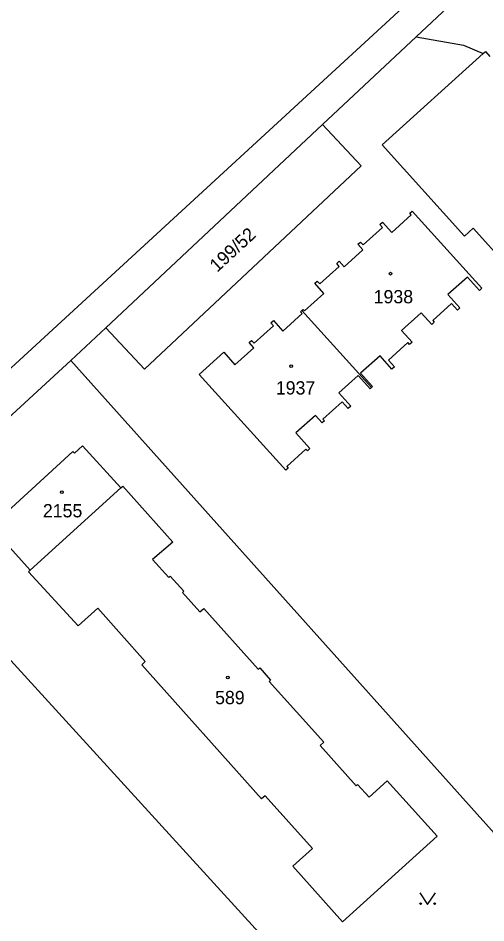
# Model space of a CAD drawing. Extents: x -735249 to -729401, y -1124843 to -1121828.
# Drawn here: x -733187.6 to -733127.6, y -1123687.3 to -1123571.3 of the extents above; entities that cross this region are included whole.
import ezdxf

# ---------------------------------------------------------------- set-up
doc = ezdxf.new("R2010")
doc.units = 0
for name, color, linetype in [('Vrstva 1', 7, 'Continuous'), ('Vrstva 18', 7, 'Continuous'), ('Vrstva 19', 7, 'Continuous'), ('Vrstva 25', 7, 'Continuous'), ('Vrstva 4', 7, 'Continuous')]:
    doc.layers.add(name, color=color, linetype=linetype)

msp = doc.modelspace()

# ---------------------------------------------------------------- linework, layer by layer
at = {"layer": 'Vrstva 1'}
for points in [[(-733136.55, -1123573.69), (-733127.8, -1123565.48)], [(-733195.46, -1123622.51), (-733137.81, -1123569.53)], [(-733136.55, -1123573.69), (-733148.57, -1123584.95)], [(-733136.55, -1123573.69), (-733130.49, -1123574.79)], [(-733130.49, -1123574.79), (-733127.95, -1123575.86)], [(-733140.9, -1123587.54), (-733127.95, -1123575.86)], [(-733148.57, -1123584.95), (-733176.35, -1123611.01)], [(-733148.57, -1123584.95), (-733143.6, -1123590.26)], [(-733130.35, -1123599.25), (-733140.9, -1123587.54)], [(-733143.6, -1123590.26), (-733171.38, -1123616.32)], [(-733139.67, -1123598.8), (-733137.17, -1123596.54)], [(-733137.37, -1123596.32), (-733137.06, -1123596.04)], [(-733137.17, -1123596.54), (-733137.37, -1123596.32)], [(-733137.06, -1123596.04), (-733128.11, -1123605.94)], [(-733143.36, -1123600.38), (-733140.86, -1123598.13)], [(-733141.19, -1123597.76), (-733140.87, -1123597.47)], [(-733140.86, -1123598.13), (-733141.19, -1123597.76)], [(-733140.87, -1123597.47), (-733139.67, -1123598.8)], [(-733129.22, -1123598.23), (-733130.35, -1123599.25)], [(-733124.9, -1123603.03), (-733129.22, -1123598.23)], [(-733144.02, -1123600.3), (-733143.7, -1123600.01)], [(-733143.39, -1123601.01), (-733144.02, -1123600.3)], [(-733143.7, -1123600.01), (-733143.36, -1123600.38)], [(-733145.79, -1123603.18), (-733143.39, -1123601.01)], [(-733146.74, -1123602.76), (-733146.42, -1123602.47)], [(-733146.41, -1123603.13), (-733146.74, -1123602.76)], [(-733146.42, -1123602.47), (-733145.79, -1123603.18)], [(-733148.91, -1123605.38), (-733146.41, -1123603.13)], [(-733149.55, -1123605.29), (-733149.24, -1123605.01)], [(-733149.24, -1123605.01), (-733148.91, -1123605.38)], [(-733129.97, -1123604.51), (-733132.47, -1123606.76)], [(-733128.43, -1123606.23), (-733129.97, -1123604.51)], [(-733148.38, -1123606.6), (-733149.55, -1123605.29)], [(-733128.11, -1123605.94), (-733128.43, -1123606.23)], [(-733150.87, -1123608.85), (-733148.38, -1123606.6)], [(-733132.47, -1123606.76), (-733130.93, -1123608.47)], [(-733151.22, -1123608.81), (-733151.05, -1123608.66)], [(-733151.05, -1123608.66), (-733150.87, -1123608.85)], [(-733132.01, -1123607.91), (-733134.42, -1123610.08)], [(-733131.25, -1123608.76), (-733132.01, -1123607.91)], [(-733130.93, -1123608.47), (-733131.25, -1123608.76)], [(-733153.66, -1123611.42), (-733151.17, -1123609.18)], [(-733151.37, -1123608.95), (-733151.22, -1123608.81)], [(-733151.17, -1123609.18), (-733151.37, -1123608.95)], [(-733151.22, -1123608.81), (-733142.3, -1123618.68)], [(-733135.9, -1123609.08), (-733138.43, -1123611.34)], [(-733134.54, -1123610.59), (-733135.9, -1123609.08)], [(-733180.84, -1123615.22), (-733176.35, -1123611.01)], [(-733171.38, -1123616.32), (-733176.35, -1123611.01)], [(-733157.33, -1123612.99), (-733154.84, -1123610.74)], [(-733155.18, -1123610.37), (-733154.86, -1123610.08)], [(-733154.84, -1123610.74), (-733155.18, -1123610.37)], [(-733154.86, -1123610.08), (-733153.66, -1123611.42)], [(-733134.22, -1123610.3), (-733134.54, -1123610.59)], [(-733134.42, -1123610.08), (-733134.22, -1123610.3)], [(-733138.43, -1123611.34), (-733137.07, -1123612.86)], [(-733157.99, -1123612.9), (-733157.67, -1123612.62)], [(-733157.39, -1123613.57), (-733157.99, -1123612.9)], [(-733157.67, -1123612.62), (-733157.33, -1123612.99)], [(-733137.61, -1123612.9), (-733140.11, -1123615.14)], [(-733137.39, -1123613.14), (-733137.61, -1123612.9)], [(-733137.07, -1123612.86), (-733137.39, -1123613.14)], [(-733164.39, -1123617), (-733161.22, -1123614.14)], [(-733161.22, -1123614.14), (-733159.79, -1123615.74)], [(-733159.79, -1123615.74), (-733157.39, -1123613.57)], [(-733201.34, -1123634.01), (-733180.84, -1123615.22)], [(-733180.84, -1123615.22), (-733120.65, -1123682.36)], [(-733141.18, -1123614.59), (-733143.67, -1123616.83)], [(-733139.65, -1123616.3), (-733141.18, -1123614.59)], [(-733140.11, -1123615.14), (-733139.33, -1123616.01)], [(-733143.67, -1123616.83), (-733142.13, -1123618.53)], [(-733139.33, -1123616.01), (-733139.65, -1123616.3)], [(-733153.28, -1123629.28), (-733164.39, -1123617)], [(-733143.99, -1123617.12), (-733146.49, -1123619.36)], [(-733142.46, -1123618.83), (-733143.99, -1123617.12)], [(-733142.3, -1123618.68), (-733142.46, -1123618.83)], [(-733142.13, -1123618.53), (-733142.3, -1123618.68)], [(-733146.49, -1123619.36), (-733144.95, -1123621.07)], [(-733146.05, -1123620.51), (-733148.5, -1123622.71)], [(-733145.28, -1123621.36), (-733146.05, -1123620.51)], [(-733144.95, -1123621.07), (-733145.28, -1123621.36)], [(-733149.48, -1123622.25), (-733151.97, -1123624.48)], [(-733148.62, -1123623.21), (-733149.48, -1123622.25)], [(-733148.3, -1123622.93), (-733148.62, -1123623.21)], [(-733148.5, -1123622.71), (-733148.3, -1123622.93)], [(-733151.97, -1123624.48), (-733150.17, -1123626.49)], [(-733180.39, -1123627.09), (-733179.34, -1123626.15)], [(-733179.34, -1123626.15), (-733174.43, -1123631.54)], [(-733190.1, -1123635.52), (-733180.6, -1123626.87)], [(-733180.6, -1123626.87), (-733180.39, -1123627.09)], [(-733150.69, -1123626.55), (-733153.16, -1123628.77)], [(-733150.49, -1123626.77), (-733150.69, -1123626.55)], [(-733150.17, -1123626.49), (-733150.49, -1123626.77)], [(-733152.96, -1123628.99), (-733153.28, -1123629.28)], [(-733153.16, -1123628.77), (-733152.96, -1123628.99)], [(-733186.04, -1123642.09), (-733174.43, -1123631.54)], [(-733174.43, -1123631.54), (-733174.19, -1123631.32)], [(-733174.19, -1123631.32), (-733167.77, -1123638.47)], [(-733190.95, -1123636.69), (-733186.04, -1123642.09)], [(-733167.77, -1123638.47), (-733170.35, -1123640.71)], [(-733170.35, -1123640.71), (-733168.28, -1123643.01)], [(-733186.04, -1123642.09), (-733186.28, -1123642.31)], [(-733186.28, -1123642.31), (-733179.92, -1123649.23)], [(-733168.28, -1123643.01), (-733168.1, -1123642.84)], [(-733168.1, -1123642.84), (-733166.34, -1123644.79)], [(-733166.34, -1123644.79), (-733166.53, -1123644.95)], [(-733166.53, -1123644.95), (-733164.29, -1123647.44)], [(-733150.58, -1123695.3), (-733194.79, -1123646.86)], [(-733177.38, -1123646.96), (-733179.92, -1123649.23)], [(-733171.29, -1123653.77), (-733177.38, -1123646.96)], [(-733164.29, -1123647.44), (-733163.8, -1123647.01)], [(-733163.8, -1123647.01), (-733156.8, -1123654.79)], [(-733171.75, -1123654.23), (-733171.29, -1123653.77)], [(-733156.37, -1123671.4), (-733171.75, -1123654.23)], [(-733156.8, -1123654.79), (-733156.61, -1123654.62)], [(-733156.61, -1123654.62), (-733155.22, -1123656.17)], [(-733155.22, -1123656.17), (-733155.4, -1123656.34)], [(-733155.4, -1123656.34), (-733148.4, -1123664.14)], [(-733148.4, -1123664.14), (-733148.88, -1123664.56)], [(-733148.88, -1123664.56), (-733144.25, -1123669.71)], [(-733144.25, -1123669.71), (-733144.06, -1123669.54)], [(-733144.06, -1123669.54), (-733142.58, -1123671.18)], [(-733142.58, -1123671.18), (-733140.25, -1123669.08)], [(-733140.25, -1123669.08), (-733133.85, -1123676.19)], [(-733155.9, -1123671), (-733156.37, -1123671.4)], [(-733149.84, -1123677.78), (-733155.9, -1123671)], [(-733133.85, -1123676.19), (-733145.98, -1123687.18)], [(-733152.36, -1123680.03), (-733149.84, -1123677.78)], [(-733145.98, -1123687.18), (-733152.36, -1123680.03)]]:
    msp.add_lwpolyline(points, dxfattribs=at)
at = {"layer": 'Vrstva 25'}
msp.add_lwpolyline([(-733136.08, -1123683.43), (-733135.08, -1123684.93), (-733134.08, -1123683.43)], dxfattribs=at)
for centre, radius in [((-733139.83, -1123604.07), 0.175), ((-733152.59, -1123615.92), 0.175), ((-733182, -1123632.09), 0.175), ((-733160.72, -1123655.85), 0.175), ((-733135.98, -1123684.83), 0.1), ((-733134.18, -1123684.83), 0.1)]:
    msp.add_circle(centre, radius, dxfattribs=at)
at = {"layer": 'Vrstva 4'}
for points in [[(-733127.95, -1123575.86), (-733127.67, -1123575.58)], [(-733127.67, -1123575.58), (-733127.08, -1123576.22)]]:
    msp.add_lwpolyline(points, dxfattribs=at)

# ---------------------------------------------------------------- texts
at = {"layer": 'Vrstva 18'}
msp.add_text('199/52', height=1.7, rotation=42.70034, dxfattribs=at).set_placement((-733162.079, -1123603.968))
at = {"layer": 'Vrstva 19'}
for s, p in [('1938', (-733142, -1123607.87)), ('1937', (-733154.55, -1123619.56)), ('2155', (-733184.43, -1123635.31)), ('589', (-733162.34, -1123659.26))]:
    msp.add_text(s, height=1.7, dxfattribs=at).set_placement(p)

doc.saveas('drawing.dxf')
